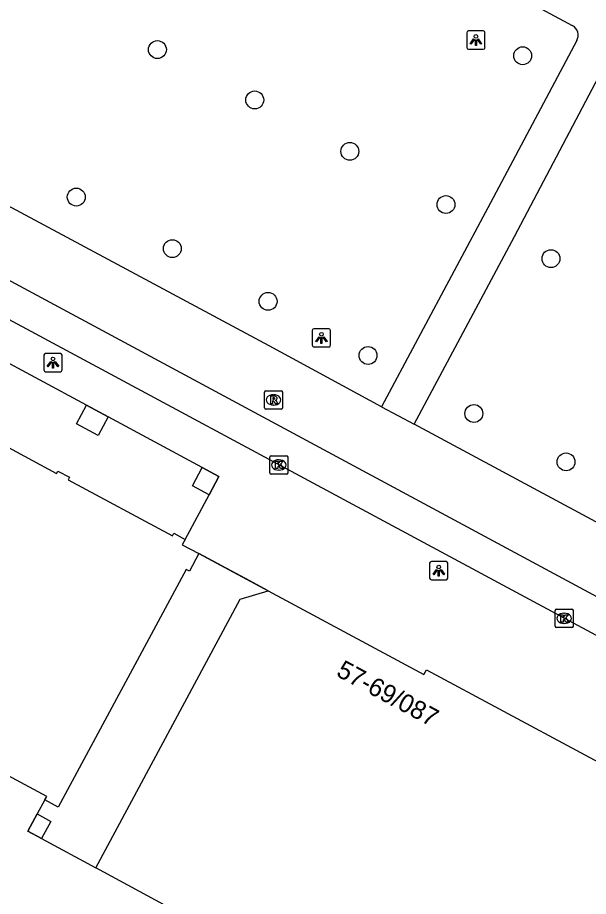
# Model space of a CAD drawing. Extents: x 159489 to 160304, y 383826 to 384530.
# Drawn here: x 159737.61 to 159768.87, y 384170.41 to 384218.51 of the extents above; entities that cross this region are included whole.
import ezdxf

# ---------------------------------------------------------------- set-up
doc = ezdxf.new("R2010")
doc.units = 0
for name, color, linetype in [('IMGEO_Boom', 7, 'Continuous'), ('IMGEO_Kolk', 7, 'Continuous'), ('IMGEO_Lichtpunt', 7, 'Continuous'), ('IMGEO_Pand', 7, 'Continuous'), ('IMGEO_Pand_nummerreeks', 7, 'Continuous'), ('IMGEO_Pand_overbouw', 7, 'Continuous'), ('IMGEO_Rijbaan_lokaal_gesloten', 7, 'Continuous'), ('IMGEO_Rioolput', 7, 'Continuous'), ('IMGEO_Voetgangersgebied_gesloten', 7, 'Continuous'), ('IMGEO_Voetpad_open', 7, 'Continuous')]:
    doc.layers.add(name, color=color, linetype=linetype)

msp = doc.modelspace()

# ---------------------------------------------------------------- linework, layer by layer
at = {"layer": 'IMGEO_Boom'}
for centre in [(159745.271, 384216.762), (159765.269, 384216.425), (159750.6, 384214.007), (159755.806, 384211.193), (159740.828, 384208.69), (159761.068, 384208.28), (159746.088, 384205.87), (159766.818, 384205.321), (159751.33, 384202.981), (159756.802, 384200.021), (159762.598, 384196.842), (159767.643, 384194.196)]:
    msp.add_circle(centre, 0.489, dxfattribs=at)
at = {"layer": 'IMGEO_Kolk'}
for p, q in [((159751.419, 384193.604), (159751.419, 384194.456)), ((159751.494, 384194.53), (159752.346, 384194.53)), ((159751.907, 384194.31), (159751.932, 384194.31)), ((159752.42, 384194.456), (159752.42, 384193.604)), ((159751.93, 384193.75), (159751.905, 384193.75)), ((159752.346, 384193.53), (159751.494, 384193.53)), ((159767.041, 384185.207), (159767.041, 384186.059)), ((159767.116, 384186.133), (159767.968, 384186.133)), ((159768.042, 384186.059), (159768.042, 384185.207)), ((159767.529, 384185.913), (159767.554, 384185.913)), ((159767.968, 384185.133), (159767.116, 384185.133)), ((159767.552, 384185.353), (159767.527, 384185.353))]:
    msp.add_line(p, q, dxfattribs=at)
for points in [[(159751.419, 384193.604), (159751.419, 384194.456)], [(159751.494, 384194.53), (159752.346, 384194.53)], [(159751.74, 384194.23), (159751.863, 384194.23), (159751.863, 384194.079), (159751.993, 384194.23), (159752.157, 384194.23), (159752.011, 384194.079), (159752.164, 384193.83), (159752.012, 384193.83), (159751.927, 384193.994), (159751.863, 384193.927), (159751.863, 384193.83), (159751.74, 384193.83), (159751.74, 384194.23)], [(159752.42, 384194.456), (159752.42, 384193.604)], [(159752.346, 384193.53), (159751.494, 384193.53)], [(159767.041, 384185.207), (159767.041, 384186.059)], [(159767.116, 384186.133), (159767.968, 384186.133)], [(159768.042, 384186.059), (159768.042, 384185.207)], [(159767.362, 384185.833), (159767.485, 384185.833), (159767.485, 384185.682), (159767.615, 384185.833), (159767.779, 384185.833), (159767.633, 384185.682), (159767.786, 384185.433), (159767.634, 384185.433), (159767.549, 384185.597), (159767.485, 384185.53), (159767.485, 384185.433), (159767.362, 384185.433), (159767.362, 384185.833)], [(159767.968, 384185.133), (159767.116, 384185.133)]]:
    msp.add_lwpolyline(points, dxfattribs=at)
for centre, start, end in [((159751.496, 384194.454), 91.552, 178.448), ((159751.496, 384194.454), 91.552, 178.448), ((159752.344, 384194.454), 1.552, 88.448), ((159752.344, 384194.454), 1.552, 88.448), ((159751.496, 384193.606), 181.552, 268.448), ((159751.496, 384193.606), 181.552, 268.448), ((159752.344, 384193.606), 271.552, 358.448), ((159752.344, 384193.606), 271.552, 358.448), ((159767.118, 384186.057), 91.552, 178.448), ((159767.118, 384186.057), 91.552, 178.448), ((159767.966, 384186.057), 1.552, 88.448), ((159767.966, 384186.057), 1.552, 88.448), ((159767.118, 384185.209), 181.552, 268.448), ((159767.118, 384185.209), 181.552, 268.448), ((159767.966, 384185.209), 271.552, 358.448), ((159767.966, 384185.209), 271.552, 358.448)]:
    msp.add_arc(centre, 0.0765, start, end, dxfattribs=at)
for centre, major_axis, ratio, start_param, end_param in [((159751.906, 384194.03), (-0.387, 0.002), 0.722429, 4.712389, 7.853982), ((159751.931, 384194.03), (-0.39, 0.002), 0.717154, 1.570796, 4.712389), ((159767.528, 384185.633), (-0.387, 0.002), 0.722429, 4.712389, 7.853982), ((159767.553, 384185.633), (-0.39, 0.002), 0.717154, 1.570796, 4.712389)]:
    msp.add_ellipse(centre, major_axis=major_axis, ratio=ratio, start_param=start_param, end_param=end_param, dxfattribs=at)
at = {"layer": 'IMGEO_Lichtpunt'}
for p, q in [((159763.112, 384217.78), (159762.304, 384217.78)), ((159763.112, 384217.78), (159762.304, 384217.78)), ((159762.21, 384217.685), (159762.21, 384216.878)), ((159762.21, 384217.685), (159762.21, 384216.878)), ((159763.206, 384216.878), (159763.206, 384217.685)), ((159763.206, 384216.878), (159763.206, 384217.685)), ((159762.304, 384216.784), (159763.112, 384216.784)), ((159762.304, 384216.784), (159763.112, 384216.784)), ((159754.652, 384201.481), (159753.844, 384201.481)), ((159754.652, 384201.481), (159753.844, 384201.481)), ((159753.75, 384201.386), (159753.75, 384200.579)), ((159753.75, 384201.386), (159753.75, 384200.579)), ((159754.746, 384200.579), (159754.746, 384201.386)), ((159754.746, 384200.579), (159754.746, 384201.386)), ((159753.844, 384200.485), (159754.652, 384200.485)), ((159753.844, 384200.485), (159754.652, 384200.485)), ((159739.055, 384200.034), (159739.055, 384199.227)), ((159739.055, 384200.034), (159739.055, 384199.227)), ((159739.957, 384200.129), (159739.149, 384200.129)), ((159739.957, 384200.129), (159739.149, 384200.129)), ((159740.051, 384199.227), (159740.051, 384200.034)), ((159740.051, 384199.227), (159740.051, 384200.034)), ((159739.149, 384199.133), (159739.957, 384199.133)), ((159739.149, 384199.133), (159739.957, 384199.133)), ((159760.174, 384188.645), (159760.174, 384187.838)), ((159760.174, 384188.645), (159760.174, 384187.838)), ((159761.076, 384188.74), (159760.268, 384188.74)), ((159761.076, 384188.74), (159760.268, 384188.74)), ((159761.17, 384187.838), (159761.17, 384188.645)), ((159761.17, 384187.838), (159761.17, 384188.645)), ((159760.268, 384187.744), (159761.076, 384187.744)), ((159760.268, 384187.744), (159761.076, 384187.744))]:
    msp.add_line(p, q, dxfattribs=at)
for points in [[(159762.584, 384217.349), (159762.623, 384217.321), (159762.435, 384217.059), (159762.397, 384217.086), (159762.584, 384217.349)], [(159762.686, 384217.301), (159762.733, 384217.301), (159762.733, 384216.979), (159762.686, 384216.979), (159762.686, 384217.301)], [(159762.796, 384217.321), (159762.834, 384217.348), (159763.021, 384217.086), (159762.982, 384217.058), (159762.796, 384217.321)], [(159754.124, 384201.05), (159754.163, 384201.022), (159753.975, 384200.76), (159753.937, 384200.787), (159754.124, 384201.05)], [(159754.226, 384201.002), (159754.273, 384201.002), (159754.273, 384200.68), (159754.226, 384200.68), (159754.226, 384201.002)], [(159754.336, 384201.022), (159754.374, 384201.049), (159754.561, 384200.787), (159754.522, 384200.759), (159754.336, 384201.022)], [(159739.429, 384199.698), (159739.468, 384199.67), (159739.28, 384199.408), (159739.242, 384199.435), (159739.429, 384199.698)], [(159739.531, 384199.65), (159739.578, 384199.65), (159739.578, 384199.328), (159739.531, 384199.328), (159739.531, 384199.65)], [(159739.641, 384199.67), (159739.679, 384199.697), (159739.866, 384199.435), (159739.827, 384199.407), (159739.641, 384199.67)], [(159760.548, 384188.309), (159760.587, 384188.281), (159760.399, 384188.019), (159760.361, 384188.046), (159760.548, 384188.309)], [(159760.65, 384188.261), (159760.697, 384188.261), (159760.697, 384187.939), (159760.65, 384187.939), (159760.65, 384188.261)], [(159760.76, 384188.281), (159760.798, 384188.308), (159760.985, 384188.046), (159760.946, 384188.018), (159760.76, 384188.281)]]:
    msp.add_lwpolyline(points, dxfattribs=at)
for centre in [(159762.709, 384217.483), (159754.249, 384201.184), (159739.554, 384199.832), (159760.673, 384188.443)]:
    msp.add_circle(centre, 0.0994, dxfattribs=at)
for centre, start, end in [((159762.304, 384217.685), 90, 180), ((159762.304, 384217.685), 90, 180), ((159763.112, 384217.685), 0, 90), ((159763.112, 384217.685), 0, 90), ((159762.304, 384216.878), 180, 270), ((159762.304, 384216.878), 180, 270), ((159763.112, 384216.878), 270, 0), ((159763.112, 384216.878), 270, 360), ((159753.844, 384201.386), 90, 180), ((159753.844, 384201.386), 90, 180), ((159754.652, 384201.386), 0, 90), ((159754.652, 384201.386), 0, 90), ((159753.844, 384200.579), 180, 270), ((159753.844, 384200.579), 180, 270), ((159754.652, 384200.579), 270, 0), ((159754.652, 384200.579), 270, 360), ((159739.149, 384200.034), 90, 180), ((159739.149, 384200.034), 90, 180), ((159739.957, 384200.034), 0, 90), ((159739.957, 384200.034), 0, 90), ((159739.149, 384199.227), 180, 270), ((159739.149, 384199.227), 180, 270), ((159739.957, 384199.227), 270, 0), ((159739.957, 384199.227), 270, 360), ((159760.268, 384188.645), 90, 180), ((159760.268, 384188.645), 90, 180), ((159761.076, 384188.645), 0, 90), ((159761.076, 384188.645), 0, 90), ((159760.268, 384187.838), 180, 270), ((159760.268, 384187.838), 180, 270), ((159761.076, 384187.838), 270, 0), ((159761.076, 384187.838), 270, 360)]:
    msp.add_arc(centre, 0.0946, start, end, dxfattribs=at)
at = {"layer": 'IMGEO_Pand'}
for points in [[(159720.655, 384203.689), (159720.717, 384203.806), (159720.79, 384203.943), (159721.416, 384203.608), (159721.342, 384203.47), (159727.068, 384200.388), (159727.142, 384200.524), (159727.767, 384200.188), (159727.693, 384200.051), (159733.414, 384196.972), (159733.488, 384197.109), (159734.113, 384196.772), (159734.039, 384196.636), (159739.755, 384193.56), (159739.828, 384193.696), (159740.454, 384193.36), (159740.38, 384193.223), (159746.088, 384190.151), (159746.162, 384190.288), (159746.787, 384189.951), (159746.713, 384189.815), (159746.633, 384189.666), (159747.543, 384189.177)], [(159747.543, 384189.177), (159747.022, 384188.208), (159746.853, 384188.299), (159739.845, 384175.298), (159739.116, 384175.702), (159739.215, 384175.882), (159713.256, 384189.858), (159720.655, 384203.689)], [(159742.031, 384195.648), (159740.842, 384196.288), (159741.392, 384197.298), (159742.576, 384196.661), (159742.031, 384195.648)], [(159748.098, 384192.387), (159747.184, 384192.879), (159747.728, 384193.892), (159748.642, 384193.4), (159748.098, 384192.387)], [(159759.218, 384131.522), (159742.655, 384140.419), (159750.036, 384154.135), (159747.85, 384155.324), (159753.455, 384165.727), (159741.891, 384171.976), (159749.801, 384186.691), (159751.335, 384187.138)], [(159751.335, 384187.138), (159759.86, 384182.554), (159760.006, 384182.817), (159781.081, 384171.509)], [(159738.176, 384173.983), (159738.687, 384174.929), (159739.428, 384174.524), (159738.92, 384173.581), (159738.176, 384173.983)]]:
    msp.add_lwpolyline(points, dxfattribs=at)
at = {"layer": 'IMGEO_Pand_overbouw'}
msp.add_lwpolyline([(159734.039, 384196.636), (159739.755, 384193.56), (159739.828, 384193.696), (159740.454, 384193.36), (159740.38, 384193.223), (159746.088, 384190.151), (159746.162, 384190.288), (159746.787, 384189.951), (159748.098, 384192.387), (159748.642, 384193.4), (159747.728, 384193.892), (159742.576, 384196.661), (159741.392, 384197.298), (159736.232, 384200.072)], dxfattribs=at)
msp.add_lwpolyline([(159751.335, 384187.138), (159750.331, 384187.678), (159747.543, 384189.177), (159747.022, 384188.208), (159746.853, 384188.299), (159739.845, 384175.298), (159739.116, 384175.702), (159738.687, 384174.929), (159738.176, 384173.983), (159738.92, 384173.581), (159741.891, 384171.976), (159749.801, 384186.691)], close=True, dxfattribs=at)
at = {"layer": 'IMGEO_Rijbaan_lokaal_gesloten'}
for points in [[(159757.536, 384197.201), (159751.393, 384200.54), (159714.889, 384220.13)], [(159716.588, 384213.02), (159717.497, 384214.699), (159780.53, 384180.797), (159779.651, 384179.125)], [(159757.536, 384197.201), (159759.321, 384196.257)], [(159855.536, 384144.567), (159759.321, 384196.257)]]:
    msp.add_lwpolyline(points, dxfattribs=at)
at = {"layer": 'IMGEO_Rioolput'}
for p, q in [((159751.202, 384198.089), (159752.054, 384198.089)), ((159751.127, 384197.163), (159751.127, 384198.015)), ((159751.615, 384197.869), (159751.64, 384197.869)), ((159752.128, 384198.015), (159752.128, 384197.163)), ((159752.054, 384197.089), (159751.202, 384197.089)), ((159751.638, 384197.309), (159751.613, 384197.309))]:
    msp.add_line(p, q, dxfattribs=at)
for points in [[(159751.202, 384198.089), (159752.054, 384198.089)], [(159751.127, 384197.163), (159751.127, 384198.015)], [(159751.716, 384197.787), (159751.464, 384197.789), (159751.464, 384197.389)], [(159751.642, 384197.708), (159751.588, 384197.708), (159751.588, 384197.627)], [(159751.588, 384197.627), (159751.64, 384197.627)], [(159752.128, 384198.015), (159752.128, 384197.163)], [(159752.054, 384197.089), (159751.202, 384197.089)], [(159751.464, 384197.389), (159751.588, 384197.389), (159751.588, 384197.551), (159751.599, 384197.551)], [(159751.646, 384197.522), (159751.717, 384197.389), (159751.857, 384197.389), (159751.792, 384197.515)]]:
    msp.add_lwpolyline(points, dxfattribs=at)
for centre, radius, start, end in [((159751.204, 384198.013), 0.0765, 91.552, 178.448), ((159751.204, 384198.013), 0.0765, 91.552, 178.448), ((159752.052, 384198.013), 0.0765, 1.552, 88.448), ((159752.052, 384198.013), 0.0765, 1.552, 88.448), ((159751.624, 384197.816), 0.19, 274.7715, 282.9687), ((159751.648, 384197.612), 0.0964, 77.0061, 93.1865), ((159751.662, 384197.669), 0.0378, 276.6634, 79.6772), ((159751.715, 384197.677), 0.109, 350.3612, 89.416), ((159751.713, 384197.677), 0.112, 277.5842, 350.9817), ((159751.697, 384197.462), 0.108, 29.5134, 73.7905), ((159751.204, 384197.165), 0.0765, 181.552, 268.448), ((159751.204, 384197.165), 0.0765, 181.552, 268.448), ((159751.598, 384197.498), 0.0533, 26.0293, 88.6989), ((159752.052, 384197.165), 0.0765, 271.552, 358.448), ((159752.052, 384197.165), 0.0765, 271.552, 358.448)]:
    msp.add_arc(centre, radius, start, end, dxfattribs=at)
for centre, major_axis, ratio, start_param, end_param in [((159751.614, 384197.589), (-0.387, 0.002), 0.722429, 4.712389, 7.853982), ((159751.639, 384197.589), (-0.39, 0.002), 0.717154, 1.570796, 4.712389)]:
    msp.add_ellipse(centre, major_axis=major_axis, ratio=ratio, start_param=start_param, end_param=end_param, dxfattribs=at)
at = {"layer": 'IMGEO_Voetgangersgebied_gesloten'}
for points in [[(159713.589, 384247.309), (159767.975, 384218.084)], [(159768.226, 384217.251), (159763.508, 384208.378), (159757.536, 384197.201)], [(159759.321, 384196.257), (159764.813, 384206.538), (159769.966, 384216.295)]]:
    msp.add_lwpolyline(points, dxfattribs=at)
msp.add_arc((159767.72, 384217.553), 0.589, 329.2011, 64.3362, dxfattribs=at)
at = {"layer": 'IMGEO_Voetpad_open'}
for points in [[(159779.651, 384179.125), (159716.588, 384213.02)], [(159747.543, 384189.177), (159751.335, 384187.138)]]:
    msp.add_lwpolyline(points, dxfattribs=at)

# ---------------------------------------------------------------- texts
at = {"layer": 'IMGEO_Pand_nummerreeks'}
msp.add_text('57-69/087', height=1, rotation=331.7131, dxfattribs=at).set_placement((159755.004, 384182.513))

doc.saveas('drawing.dxf')
